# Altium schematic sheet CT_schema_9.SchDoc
size 391 x 238 mm
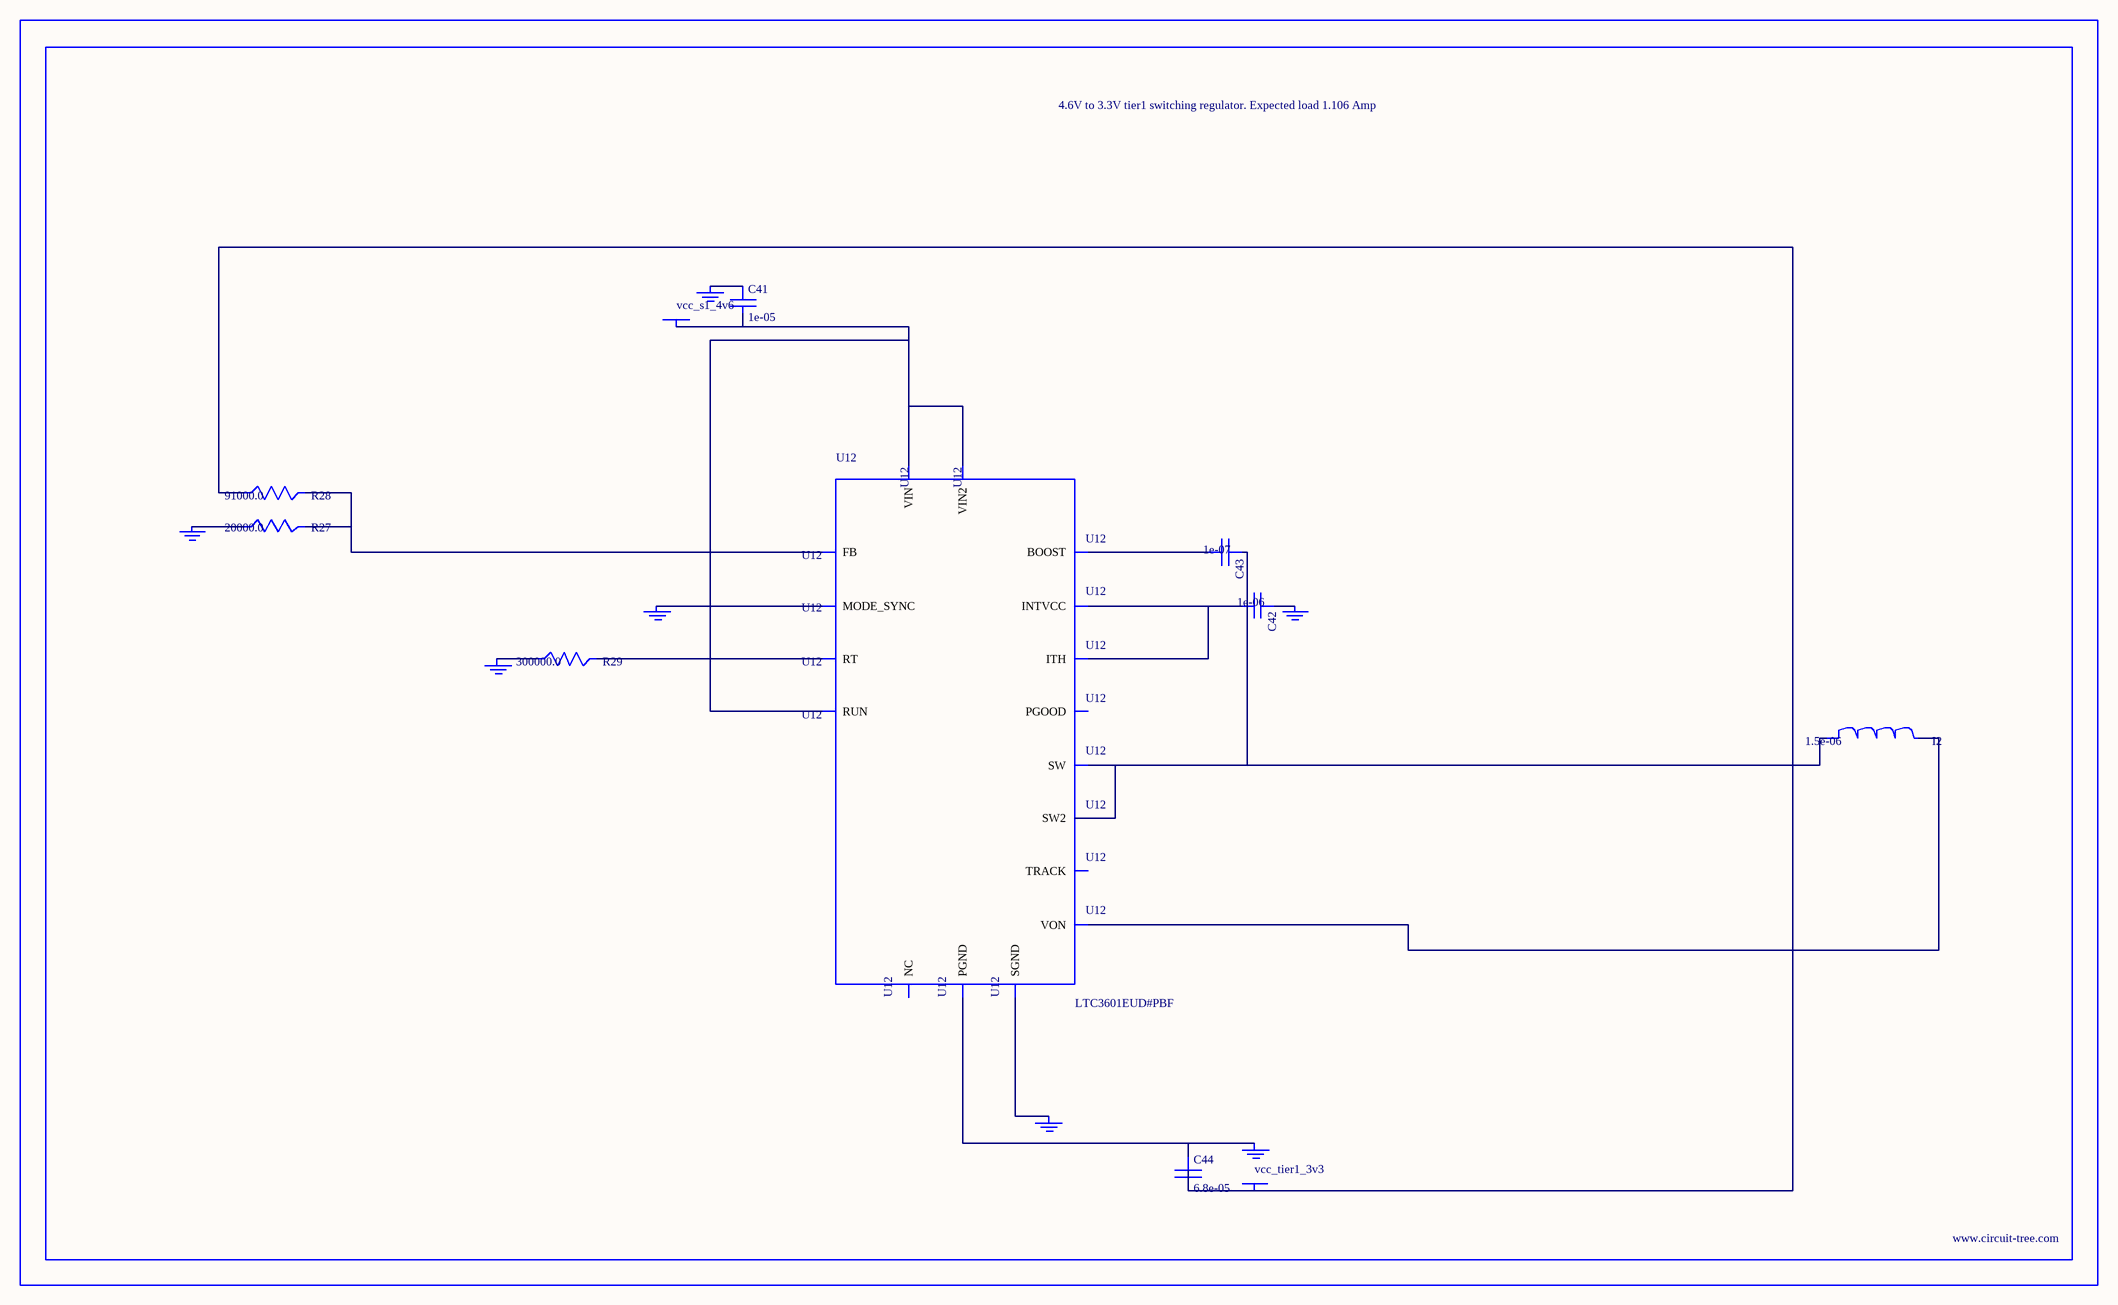
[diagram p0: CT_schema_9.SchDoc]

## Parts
BORDER8  (no value)
C41  1e-05  [C0805]
C42  1e-06  [C0603]
C43  1e-07  [C0402]
C44  6.8e-05  [2220]
GND_INSTANCE_8_0  (no value)
GND_INSTANCE_8_1  (no value)
GND_INSTANCE_8_2  (no value)
GND_INSTANCE_8_3  (no value)
GND_INSTANCE_8_4  (no value)
GND_INSTANCE_8_5  (no value)
GND_INSTANCE_8_6  (no value)
I2  1.5e-06  [IND_PM3316]
POWER_INSTANCE_8_0  vcc_s1_4v6
POWER_INSTANCE_8_1  vcc_tier1_3v3
R27  20000.0  [R0603]
R28  91000.0  [R0603]
R29  300000.0  [R0603]
U12  LTC3601EUD#PBF  [QFN-16_EP]

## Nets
NetC41_1: C41.1 GND_INSTANCE_8_5.0(GND)
NetC41_2: C41.2 POWER_INSTANCE_8_0.0(PWR) U12.14(RUN) U12.15(VIN) U12.16(VIN2)
NetC42_1: C42.1 GND_INSTANCE_8_1.0(GND)
NetC42_2: C42.2 U12.7(INTVCC) U12.12(ITH)
NetC43_1: C43.1 I2.1 U12.3(SW) U12.4(SW2)
NetC43_2: C43.2 U12.6(BOOST)
NetC44_1: C44.1 GND_INSTANCE_8_6.0(GND) U12.17(PGND)
NetC44_2: C44.2 I2.2 POWER_INSTANCE_8_1.0(PWR) R28.1 U12.8(VON)
NetGND_INSTANCE_8_0_0: GND_INSTANCE_8_0.0(GND) U12.1(MODE_SYNC)
NetGND_INSTANCE_8_2_0: GND_INSTANCE_8_2.0(GND) U12.9(SGND)
NetGND_INSTANCE_8_3_0: GND_INSTANCE_8_3.0(GND) R29.1
NetGND_INSTANCE_8_4_0: GND_INSTANCE_8_4.0(GND) R27.1
NetR27_2: R27.2 R28.2 U12.11(FB)
NetR29_2: R29.2 U12.10(RT)

Not connected (* = marked no-connect by the designer): U12 2(PGOOD) 5(NC) 13(TRACK)

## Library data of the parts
BORDER8 = BORDER_PAGE8
C41 = C0805C106K8RACTU
C42 = C0603C105K3RACTU
C43 = C0402C104K3RACTU
C44 = C5750X5R1A686M
GND_INSTANCE_8_0-GND_INSTANCE_8_6 = GND
I2 = PM3316-1R5M-RC
POWER_INSTANCE_8_0 POWER_INSTANCE_8_1 = PWR
R27 = RC0603JR-0720KL
R28 = RC0603JR-0791KL
R29 = RC0603JR-07300KL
